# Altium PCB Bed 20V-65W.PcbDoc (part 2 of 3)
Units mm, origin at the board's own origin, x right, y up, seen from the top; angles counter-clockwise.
Board outline 82.02 x 73.67 mm, 2 copper layers (Top Layer, Bottom Layer); 0 components, 1 nets, 2 pads, 0 vias.
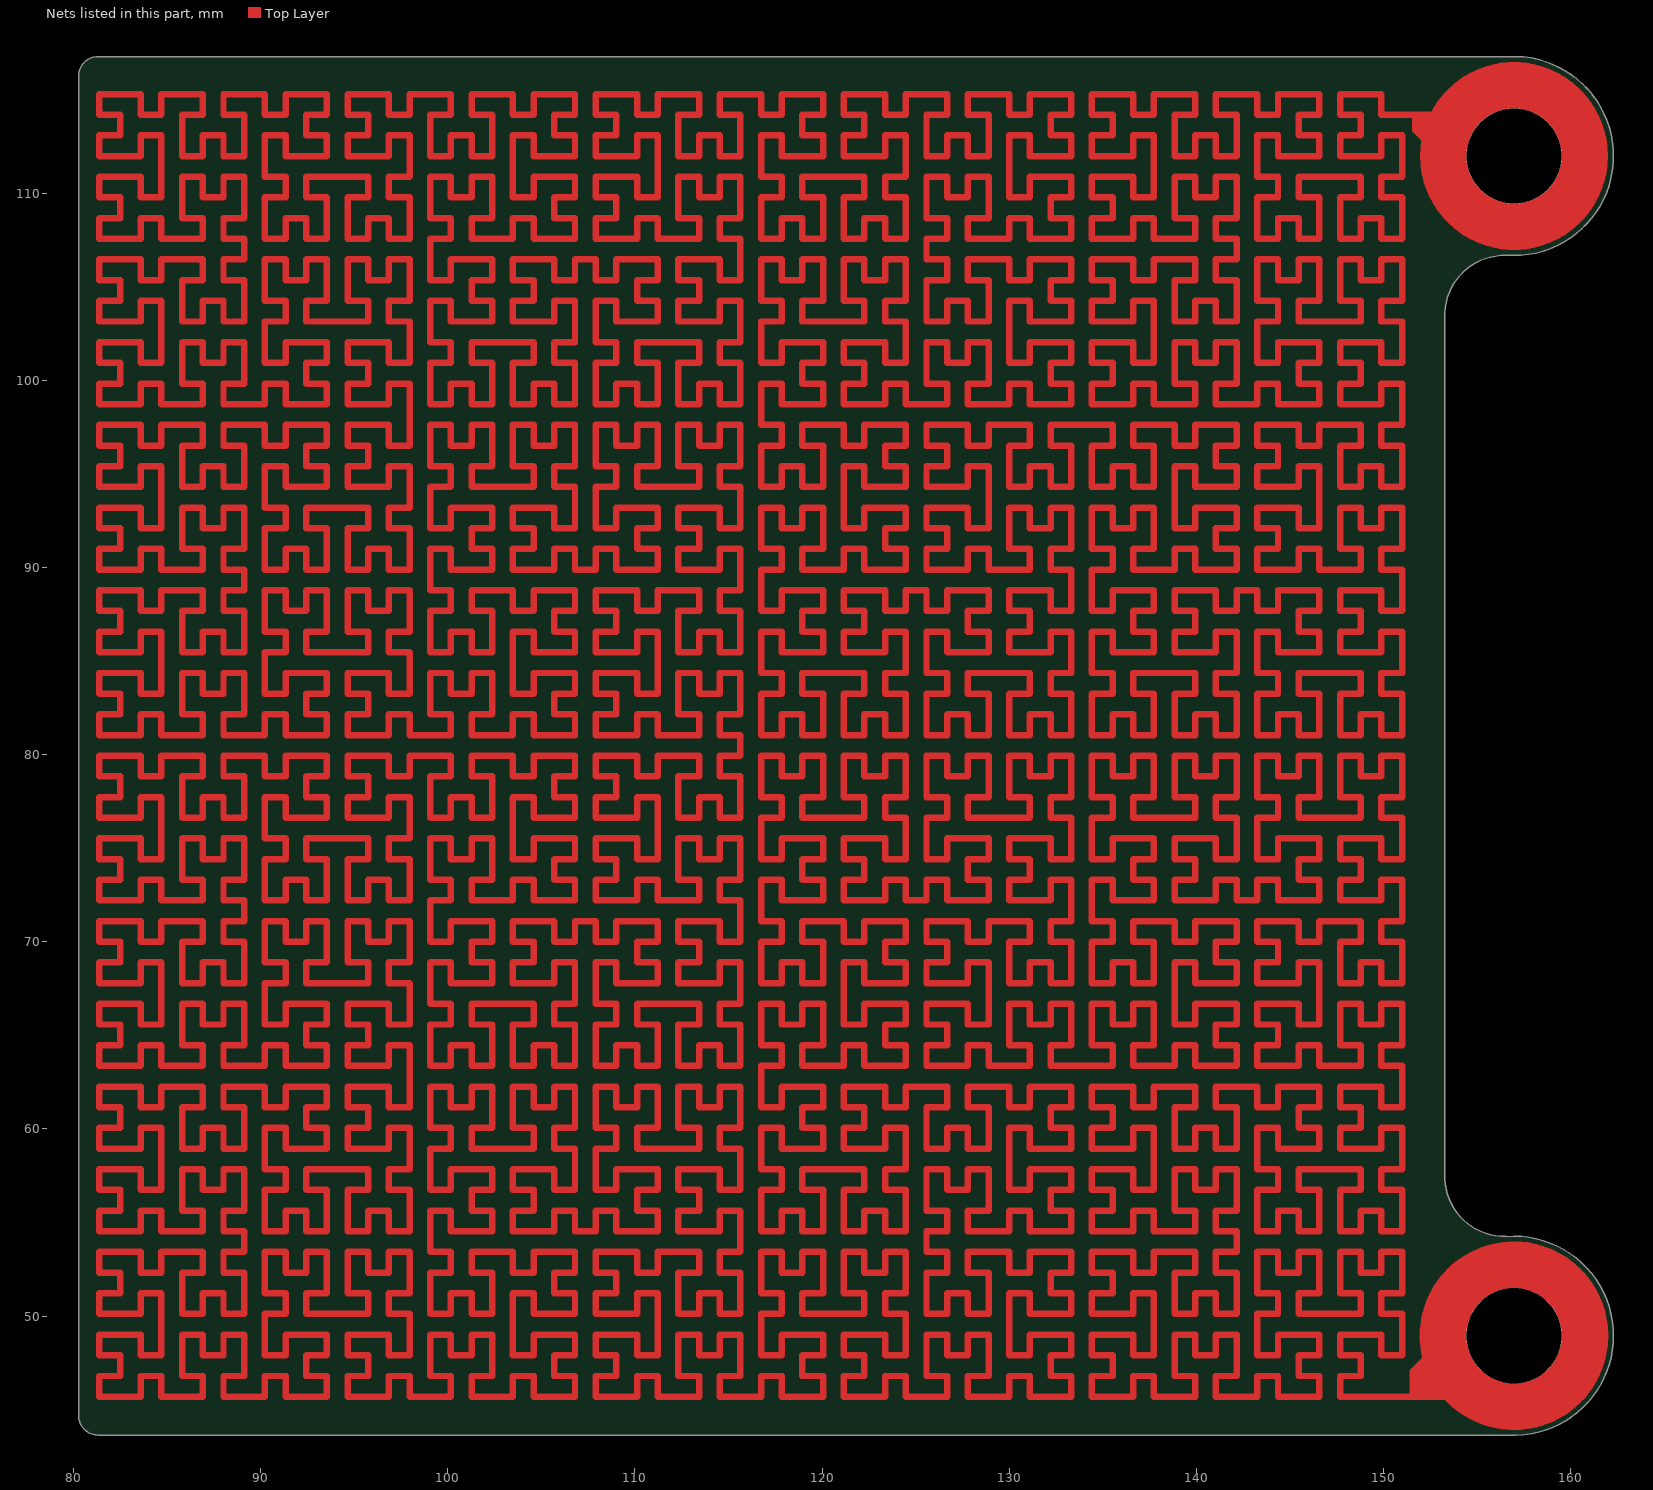
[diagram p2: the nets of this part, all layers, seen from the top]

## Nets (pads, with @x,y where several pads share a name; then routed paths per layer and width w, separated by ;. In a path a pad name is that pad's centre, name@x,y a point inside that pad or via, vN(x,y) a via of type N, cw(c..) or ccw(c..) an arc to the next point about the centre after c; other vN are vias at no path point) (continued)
Bed20V: (continued)
  Top Layer w0.346: 152.248,112.827 151.968,113.106 ; 152.756,112.725 152.222,113.259 152.222,114.193 ; 152.908,112.827 152.451,113.284 152.451,114.193 ; 153.111,112.928 152.756,113.284 152.756,114.193 ; 153.285,48.257 152.778,48.257 151.562,47.041 151.562,45.689 ; 153.34,48.031 152.857,48.031 151.841,47.015 151.841,45.689 ; 153.391,113.055 152.984,113.462 152.984,114.193 ; 153.492,47.727 152.984,47.727 152.121,46.863 152.121,45.689 ; 153.594,47.168 153.187,47.168 152.679,46.66 152.679,45.689 ; 153.594,47.447 153.111,47.447 152.4,46.736 152.4,45.689 ; 153.746,46.914 153.314,46.914 152.959,46.558 152.959,46.33 ; 153.881,114.152 153.881,114.193 152.984,114.193 ; 154.813,46.304 154.788,46.33 152.959,46.33 ; 154.864,45.974 154.82,46.018 152.959,46.018 ; 154.915,45.72 154.884,45.689 152.959,45.689 ; 151.562,45.689 151.841,45.689 ; 151.562,45.689 147.677,45.689 147.677,46.794 148.782,46.794 148.782,47.899 147.677,47.899 147.677,49.004 149.887,49.004 149.887,47.899 150.992,47.899 150.992,50.109 149.887,50.109 149.887,51.214 150.992,51.214 150.992,53.424 149.887,53.424 149.887,52.319 148.782,52.319 148.782,53.424 147.677,53.424 147.677,51.214 148.782,51.214 148.782,50.109 145.467,50.109 145.467,51.214 146.572,51.214 146.572,53.424 145.467,53.424 145.467,52.319 144.362,52.319 144.362,53.424 143.257,53.424 143.257,51.214 144.362,51.214 144.362,50.109 143.257,50.109 143.257,47.899 144.362,47.899 144.362,49.004 146.572,49.004 146.572,47.899 145.467,47.899 145.467,46.794 146.572,46.794 146.572,45.689 144.362,45.689 144.362,46.794 143.257,46.794 143.257,45.689 141.048,45.689 141.048,46.794 142.152,46.794 142.152,49.004 141.048,49.004 141.048,47.899 139.943,47.899 139.943,49.004 138.838,49.004 138.838,46.794 139.943,46.794 139.943,45.689 137.733,45.689 137.733,46.794 136.628,46.794 136.628,45.689 134.418,45.689 134.418,46.794 135.523,46.794 135.523,47.899 134.418,47.899 134.418,49.004 136.628,49.004 136.628,47.899 137.733,47.899 137.733,51.214 136.628,51.214 136.628,50.109 134.418,50.109 134.418,51.214 135.523,51.214 135.523,52.319 134.418,52.319 134.418,53.424 136.628,53.424 136.628,52.319 137.733,52.319 137.733,53.424 139.943,53.424 139.943,52.319 138.838,52.319 138.838,50.109 139.943,50.109 139.943,51.214 141.048,51.214 141.048,50.109 142.152,50.109 142.152,52.319 141.048,52.319 141.048,53.424 142.152,53.424 142.152,54.529 141.048,54.529 141.048,55.633 142.152,55.633 142.152,57.843 141.048,57.843 141.048,56.738 139.943,56.738 139.943,57.843 138.838,57.843 138.838,55.633 139.943,55.633 139.943,54.529 137.733,54.529 137.733,55.633 136.628,55.633 136.628,54.529 134.418,54.529 134.418,55.633 135.523,55.633 135.523,56.738 134.418,56.738 134.418,57.843 136.628,57.843 136.628,56.738 137.733,56.738 137.733,60.053 136.628,60.053 136.628,58.948 134.418,58.948 134.418,60.053 135.523,60.053 135.523,61.158 134.418,61.158 134.418,62.263 136.628,62.263 136.628,61.158 137.733,61.158 137.733,62.263 139.943,62.263 139.943,61.158 138.838,61.158 138.838,58.948 139.943,58.948 139.943,60.053 141.048,60.053 141.048,58.948 142.152,58.948 142.152,61.158 141.048,61.158 141.048,62.263 143.257,62.263 143.257,61.158 144.362,61.158 144.362,62.263 146.572,62.263 146.572,61.158 145.467,61.158 145.467,60.053 146.572,60.053 146.572,58.948 144.362,58.948 144.362,60.053 143.257,60.053 143.257,57.843 144.362,57.843 144.362,56.738 143.257,56.738 143.257,54.529 144.362,54.529 144.362,55.633 145.467,55.633 145.467,54.529 146.572,54.529 146.572,56.738 145.467,56.738 145.467,57.843 148.782,57.843 148.782,56.738 147.677,56.738 147.677,54.529 148.782,54.529 148.782,55.633 149.887,55.633 149.887,54.529 150.992,54.529 150.992,56.738 149.887,56.738 149.887,57.843 150.992,57.843 150.992,60.053 149.887,60.053 149.887,58.948 147.677,58.948 147.677,60.053 148.782,60.053 148.782,61.158 147.677,61.158 147.677,62.263 149.887,62.263 149.887,61.158 150.992,61.158 150.992,63.368 149.887,63.368 149.887,64.473 150.992,64.473 150.992,66.682 149.887,66.682 149.887,65.578 148.782,65.578 148.782,66.682 147.677,66.682 147.677,64.473 148.782,64.473 148.782,63.368 146.572,63.368 146.572,64.473 145.467,64.473 145.467,63.368 143.257,63.368 143.257,64.473 144.362,64.473 144.362,65.578 143.257,65.578 143.257,66.682 145.467,66.682 145.467,65.578 146.572,65.578 146.572,68.892 145.467,68.892 145.467,67.787 143.257,67.787 143.257,68.892 144.362,68.892 144.362,69.997 143.257,69.997 143.257,71.102 145.467,71.102 145.467,69.997 146.572,69.997 146.572,71.102 148.782,71.102 148.782,69.997 147.677,69.997 147.677,67.787 148.782,67.787 148.782,68.892 149.887,68.892 149.887,67.787 150.992,67.787 150.992,69.997 149.887,69.997 149.887,71.102 150.992,71.102 150.992,73.312 149.887,73.312 149.887,72.207 147.677,72.207 147.677,73.312 148.782,73.312 148.782,74.417 147.677,74.417 147.677,75.522 149.887,75.522 149.887,74.417 150.992,74.417 150.992,76.627 149.887,76.627 149.887,77.731 150.992,77.731 150.992,79.941 149.887,79.941 149.887,78.836 148.782,78.836 148.782,79.941 147.677,79.941 147.677,77.731 148.782,77.731 148.782,76.627 145.467,76.627 145.467,77.731 146.572,77.731 146.572,79.941 145.467,79.941 145.467,78.836 144.362,78.836 144.362,79.941 143.257,79.941 143.257,77.731 144.362,77.731 144.362,76.627 143.257,76.627 143.257,74.417 144.362,74.417 144.362,75.522 146.572,75.522 146.572,74.417 145.467,74.417 145.467,73.312 146.572,73.312 146.572,72.207 144.362,72.207 144.362,73.312 143.257,73.312 143.257,72.207 142.152,72.207 142.152,73.312 141.048,73.312 141.048,72.207 138.838,72.207 138.838,73.312 139.943,73.312 139.943,74.417 138.838,74.417 138.838,75.522 141.048,75.522 141.048,74.417 142.152,74.417 142.152,76.627 141.048,76.627 141.048,77.731 142.152,77.731 142.152,79.941 141.048,79.941 141.048,78.836 139.943,78.836 139.943,79.941 138.838,79.941 138.838,77.731 139.943,77.731 139.943,76.627 136.628,76.627 136.628,77.731 137.733,77.731 137.733,79.941 136.628,79.941 136.628,78.836 135.523,78.836 135.523,79.941 134.418,79.941 134.418,77.731 135.523,77.731 135.523,76.627 134.418,76.627 134.418,74.417 135.523,74.417 135.523,75.522 137.733,75.522 137.733,74.417 136.628,74.417 136.628,73.312 137.733,73.312 137.733,72.207 135.523,72.207 135.523,73.312 134.418,73.312 134.418,71.102 135.523,71.102 135.523,69.997 134.418,69.997 134.418,67.787 135.523,67.787 135.523,68.892 136.628,68.892 136.628,67.787 137.733,67.787 137.733,69.997 136.628,69.997 136.628,71.102 138.838,71.102 138.838,69.997 139.943,69.997 139.943,71.102 142.152,71.102 142.152,69.997 141.048,69.997 141.048,68.892 142.152,68.892 142.152,67.787 139.943,67.787 139.943,68.892 138.838,68.892 138.838,65.578 139.943,65.578 139.943,66.682 142.152,66.682 142.152,65.578 141.048,65.578 141.048,64.473 142.152,64.473 142.152,63.368 139.943,63.368 139.943,64.473 138.838,64.473 138.838,63.368 136.628,63.368 136.628,64.473 137.733,64.473 137.733,66.682 136.628,66.682 136.628,65.578 135.523,65.578 135.523,66.682 134.418,66.682 134.418,64.473 135.523,64.473 135.523,63.368 132.208,63.368 132.208,64.473 133.313,64.473 133.313,66.682 132.208,66.682 132.208,65.578 131.103,65.578 131.103,66.682 129.999,66.682 129.999,64.473 131.103,64.473 131.103,63.368 128.894,63.368 128.894,64.473 127.789,64.473 127.789,63.368 125.579,63.368 125.579,64.473 126.684,64.473 126.684,65.578 125.579,65.578 125.579,66.682 127.789,66.682 127.789,65.578 128.894,65.578 128.894,68.892 127.789,68.892 127.789,67.787 125.579,67.787 125.579,68.892 126.684,68.892 126.684,69.997 125.579,69.997 125.579,71.102 127.789,71.102 127.789,69.997 128.894,69.997 128.894,71.102 131.103,71.102 131.103,69.997 129.999,69.997 129.999,67.787 131.103,67.787 131.103,68.892 132.208,68.892 132.208,67.787 133.313,67.787 133.313,69.997 132.208,69.997 132.208,71.102 133.313,71.102 133.313,73.312 132.208,73.312 132.208,72.207 129.999,72.207 129.999,73.312 131.103,73.312 131.103,74.417 129.999,74.417 129.999,75.522 132.208,75.522 132.208,74.417 133.313,74.417 133.313,76.627 132.208,76.627 132.208,77.731 133.313,77.731 133.313,79.941 132.208,79.941 132.208,78.836 131.103,78.836 131.103,79.941 129.999,79.941 129.999,77.731 131.103,77.731 131.103,76.627 127.789,76.627 127.789,77.731 128.894,77.731 128.894,79.941 127.789,79.941 127.789,78.836 126.684,78.836 126.684,79.941 125.579,79.941 125.579,77.731 126.684,77.731 126.684,76.627 125.579,76.627 125.579,74.417 126.684,74.417 126.684,75.522 128.894,75.522 128.894,74.417 127.789,74.417 127.789,73.312 128.894,73.312 128.894,72.207 126.684,72.207 126.684,73.312 125.579,73.312 125.579,72.207 124.474,72.207 124.474,73.312 123.369,73.312 123.369,72.207 121.159,72.207 121.159,73.312 122.264,73.312 122.264,74.417 121.159,74.417 121.159,75.522 123.369,75.522 123.369,74.417 124.474,74.417 124.474,76.627 123.369,76.627 123.369,77.731 124.474,77.731 124.474,79.941 123.369,79.941 123.369,78.836 122.264,78.836 122.264,79.941 121.159,79.941 121.159,77.731 122.264,77.731 122.264,76.627 118.95,76.627 118.95,77.731 120.054,77.731 120.054,79.941 118.95,79.941 118.95,78.836 117.845,78.836 117.845,79.941 116.74,79.941 116.74,77.731 117.845,77.731 117.845,76.627 116.74,76.627 116.74,74.417 117.845,74.417 117.845,75.522 120.054,75.522 120.054,74.417 118.95,74.417 118.95,73.312 120.054,73.312 120.054,72.207 117.845,72.207 117.845,73.312 116.74,73.312 116.74,71.102 117.845,71.102 117.845,69.997 116.74,69.997 116.74,67.787 117.845,67.787 117.845,68.892 118.95,68.892 118.95,67.787 120.054,67.787 120.054,69.997 118.95,69.997 118.95,71.102 121.159,71.102 121.159,69.997 122.264,69.997 122.264,71.102 124.474,71.102 124.474,69.997 123.369,69.997 123.369,68.892 124.474,68.892 124.474,67.787 122.264,67.787 122.264,68.892 121.159,68.892 121.159,65.578 122.264,65.578 122.264,66.682 124.474,66.682 124.474,65.578 123.369,65.578 123.369,64.473 124.474,64.473 124.474,63.368 122.264,63.368 122.264,64.473 121.159,64.473 121.159,63.368 118.95,63.368 118.95,64.473 120.054,64.473 120.054,66.682 118.95,66.682 118.95,65.578 117.845,65.578 117.845,66.682 116.74,66.682 116.74,64.473 117.845,64.473 117.845,63.368 116.74,63.368 116.74,61.158 117.845,61.158 117.845,62.263 120.054,62.263 120.054,61.158 118.95,61.158 118.95,60.053 120.054,60.053 120.054,58.948 117.845,58.948 117.845,60.053 116.74,60.053 116.74,57.843 117.845,57.843 117.845,56.738 116.74,56.738 116.74,54.529 117.845,54.529 117.845,55.633 118.95,55.633 118.95,54.529 120.054,54.529 120.054,56.738 118.95,56.738 118.95,57.843 122.264,57.843 122.264,56.738 121.159,56.738 121.159,54.529 122.264,54.529 122.264,55.633 123.369,55.633 123.369,54.529 124.474,54.529 124.474,56.738 123.369,56.738 123.369,57.843 124.474,57.843 124.474,60.053 123.369,60.053 123.369,58.948 121.159,58.948 121.159,60.053 122.264,60.053 122.264,61.158 121.159,61.158 121.159,62.263 123.369,62.263 123.369,61.158 124.474,61.158 124.474,62.263 126.684,62.263 126.684,61.158 125.579,61.158 125.579,58.948 126.684,58.948 126.684,60.053 127.789,60.053 127.789,58.948 128.894,58.948 128.894,61.158 127.789,61.158 127.789,62.263 129.999,62.263 129.999,61.158 131.103,61.158 131.103,62.263 133.313,62.263 133.313,61.158 132.208,61.158 132.208,60.053 133.313,60.053 133.313,58.948 131.103,58.948 131.103,60.053 129.999,60.053 129.999,56.738 131.103,56.738 131.103,57.843 133.313,57.843 133.313,56.738 132.208,56.738 132.208,55.633 133.313,55.633 133.313,54.529 131.103,54.529 131.103,55.633 129.999,55.633 129.999,54.529 127.789,54.529 127.789,55.633 128.894,55.633 128.894,57.843 127.789,57.843 127.789,56.738 126.684,56.738 126.684,57.843 125.579,57.843 125.579,55.633 126.684,55.633 126.684,54.529 125.579,54.529 125.579,53.424 126.684,53.424 126.684,52.319 125.579,52.319 125.579,50.109 126.684,50.109 126.684,51.214 127.789,51.214 127.789,50.109 128.894,50.109 128.894,52.319 127.789,52.319 127.789,53.424 129.999,53.424 129.999,52.319 131.103,52.319 131.103,53.424 133.313,53.424 133.313,52.319 132.208,52.319 132.208,51.214 133.313,51.214 133.313,50.109 131.103,50.109 131.103,51.214 129.999,51.214 129.999,47.899 131.103,47.899 131.103,49.004 133.313,49.004 133.313,47.899 132.208,47.899 132.208,46.794 133.313,46.794 133.313,45.689 131.103,45.689 131.103,46.794 129.999,46.794 129.999,45.689 127.789,45.689 127.789,46.794 128.894,46.794 128.894,49.004 127.789,49.004 127.789,47.899 126.684,47.899 126.684,49.004 125.579,49.004 125.579,46.794 126.684,46.794 126.684,45.689 124.474,45.689 124.474,46.794 123.369,46.794 123.369,45.689 121.159,45.689 121.159,46.794 122.264,46.794 122.264,47.899 121.159,47.899 121.159,49.004 123.369,49.004 123.369,47.899 124.474,47.899 124.474,50.109 123.369,50.109 123.369,51.214 124.474,51.214 124.474,53.424 123.369,53.424 123.369,52.319 122.264,52.319 122.264,53.424 121.159,53.424 121.159,51.214 122.264,51.214 122.264,50.109 118.95,50.109 118.95,51.214 120.054,51.214 120.054,53.424 118.95,53.424 118.95,52.319 117.845,52.319 117.845,53.424 116.74,53.424 116.74,51.214 117.845,51.214 117.845,50.109 116.74,50.109 116.74,47.899 117.845,47.899 117.845,49.004 120.054,49.004 120.054,47.899 118.95,47.899 118.95,46.794 120.054,46.794 120.054,45.689 117.845,45.689 117.845,46.794 116.74,46.794 116.74,45.689 114.53,45.689 114.53,46.794 115.635,46.794 115.635,49.004 114.53,49.004 114.53,47.899 113.425,47.899 113.425,49.004 112.32,49.004 112.32,46.794 113.425,46.794 113.425,45.689 111.215,45.689 111.215,46.794 110.11,46.794 110.11,45.689 107.901,45.689 107.901,46.794 109.005,46.794 109.005,47.899 107.901,47.899 107.901,49.004 110.11,49.004 110.11,47.899 111.215,47.899 111.215,51.214 110.11,51.214 110.11,50.109 107.901,50.109 107.901,51.214 109.005,51.214 109.005,52.319 107.901,52.319 107.901,53.424 110.11,53.424 110.11,52.319 111.215,52.319 111.215,53.424 113.425,53.424 113.425,52.319 112.32,52.319 112.32,50.109 113.425,50.109 113.425,51.214 114.53,51.214 114.53,50.109 115.635,50.109 115.635,52.319 114.53,52.319 114.53,53.424 115.635,53.424 115.635,55.633 114.53,55.633 114.53,54.529 112.32,54.529 112.32,55.633 113.425,55.633 113.425,56.738 112.32,56.738 112.32,57.843 114.53,57.843 114.53,56.738 115.635,56.738 115.635,58.948 114.53,58.948 114.53,60.053 115.635,60.053 115.635,62.263 114.53,62.263 114.53,61.158 113.425,61.158 113.425,62.263 112.32,62.263 112.32,60.053 113.425,60.053 113.425,58.948 110.11,58.948 110.11,60.053 111.215,60.053 111.215,62.263 110.11,62.263 110.11,61.158 109.005,61.158 109.005,62.263 107.901,62.263 107.901,60.053 109.005,60.053 109.005,58.948 107.901,58.948 107.901,56.738 109.005,56.738 109.005,57.843 111.215,57.843 111.215,56.738 110.11,56.738 110.11,55.633 111.215,55.633 111.215,54.529 109.005,54.529 109.005,55.633 107.901,55.633 107.901,54.529 106.796,54.529 106.796,55.633 105.691,55.633 105.691,54.529 103.481,54.529 103.481,55.633 104.586,55.633 104.586,56.738 103.481,56.738 103.481,57.843 105.691,57.843 105.691,56.738 106.796,56.738 106.796,58.948 105.691,58.948 105.691,60.053 106.796,60.053 106.796,62.263 105.691,62.263 105.691,61.158 104.586,61.158 104.586,62.263 103.481,62.263 103.481,60.053 104.586,60.053 104.586,58.948 101.271,58.948 101.271,60.053 102.376,60.053 102.376,62.263 101.271,62.263 101.271,61.158 100.166,61.158 100.166,62.263 99.061,62.263 99.061,60.053 100.166,60.053 100.166,58.948 99.061,58.948 99.061,56.738 100.166,56.738 100.166,57.843 102.376,57.843 102.376,56.738 101.271,56.738 101.271,55.633 102.376,55.633 102.376,54.529 100.166,54.529 100.166,55.633 99.061,55.633 99.061,53.424 100.166,53.424 100.166,52.319 99.061,52.319 99.061,50.109 100.166,50.109 100.166,51.214 101.271,51.214 101.271,50.109 102.376,50.109 102.376,52.319 101.271,52.319 101.271,53.424 103.481,53.424 103.481,52.319 104.586,52.319 104.586,53.424 106.796,53.424 106.796,52.319 105.691,52.319 105.691,51.214 106.796,51.214 106.796,50.109 104.586,50.109 104.586,51.214 103.481,51.214 103.481,47.899 104.586,47.899 104.586,49.004 106.796,49.004 106.796,47.899 105.691,47.899 105.691,46.794 106.796,46.794 106.796,45.689 104.586,45.689 104.586,46.794 103.481,46.794 103.481,45.689 101.271,45.689 101.271,46.794 102.376,46.794 102.376,49.004 101.271,49.004 101.271,47.899 100.166,47.899 100.166,49.004 99.061,49.004 99.061,46.794 100.166,46.794 100.166,45.689 97.956,45.689 97.956,46.794 96.852,46.794 96.852,45.689 94.642,45.689 94.642,46.794 95.747,46.794 95.747,47.899 94.642,47.899 94.642,49.004 96.852,49.004 96.852,47.899 97.956,47.899 97.956,50.109 96.852,50.109 96.852,51.214 97.956,51.214 97.956,53.424 96.852,53.424 96.852,52.319 95.747,52.319 95.747,53.424 94.642,53.424 94.642,51.214 95.747,51.214 95.747,50.109 92.432,50.109 92.432,51.214 93.537,51.214 93.537,53.424 92.432,53.424 92.432,52.319 91.327,52.319 91.327,53.424 90.222,53.424 90.222,51.214 91.327,51.214 91.327,50.109 90.222,50.109 90.222,47.899 91.327,47.899 91.327,49.004 93.537,49.004 93.537,47.899 92.432,47.899 92.432,46.794 93.537,46.794 93.537,45.689 91.327,45.689 91.327,46.794 90.222,46.794 90.222,45.689 88.012,45.689 88.012,46.794 89.117,46.794 89.117,49.004 88.012,49.004 88.012,47.899 86.907,47.899 86.907,49.004 85.803,49.004 85.803,46.794 86.907,46.794 86.907,45.689 84.698,45.689 84.698,46.794 83.593,46.794 83.593,45.689 81.383,45.689 81.383,46.794 82.488,46.794 82.488,47.899 81.383,47.899 81.383,49.004 83.593,49.004 83.593,47.899 84.698,47.899 84.698,51.214 83.593,51.214 83.593,50.109 81.383,50.109 81.383,51.214 82.488,51.214 82.488,52.319 81.383,52.319 81.383,53.424 83.593,53.424 83.593,52.319 84.698,52.319 84.698,53.424 86.907,53.424 86.907,52.319 85.803,52.319 85.803,50.109 86.907,50.109 86.907,51.214 88.012,51.214 88.012,50.109 89.117,50.109 89.117,52.319 88.012,52.319 88.012,53.424 89.117,53.424 89.117,54.529 88.012,54.529 88.012,55.633 89.117,55.633 89.117,57.843 88.012,57.843 88.012,56.738 86.907,56.738 86.907,57.843 85.803,57.843 85.803,55.633 86.907,55.633 86.907,54.529 84.698,54.529 84.698,55.633 83.593,55.633 83.593,54.529 81.383,54.529 81.383,55.633 82.488,55.633 82.488,56.738 81.383,56.738 81.383,57.843 83.593,57.843 83.593,56.738 84.698,56.738 84.698,60.053 83.593,60.053 83.593,58.948 81.383,58.948 81.383,60.053 82.488,60.053 82.488,61.158 81.383,61.158 81.383,62.263 83.593,62.263 83.593,61.158 84.698,61.158 84.698,62.263 86.907,62.263 86.907,61.158 85.803,61.158 85.803,58.948 86.907,58.948 86.907,60.053 88.012,60.053 88.012,58.948 89.117,58.948 89.117,61.158 88.012,61.158 88.012,62.263 90.222,62.263 90.222,61.158 91.327,61.158 91.327,62.263 93.537,62.263 93.537,61.158 92.432,61.158 92.432,60.053 93.537,60.053 93.537,58.948 91.327,58.948 91.327,60.053 90.222,60.053 90.222,57.843 91.327,57.843 91.327,56.738 90.222,56.738 90.222,54.529 91.327,54.529 91.327,55.633 92.432,55.633 92.432,54.529 93.537,54.529 93.537,56.738 92.432,56.738 92.432,57.843 95.747,57.843 95.747,56.738 94.642,56.738 94.642,54.529 95.747,54.529 95.747,55.633 96.852,55.633 96.852,54.529 97.956,54.529 97.956,56.738 96.852,56.738 96.852,57.843 97.956,57.843 97.956,60.053 96.852,60.053 96.852,58.948 94.642,58.948 94.642,60.053 95.747,60.053 95.747,61.158 94.642,61.158 94.642,62.263 96.852,62.263 96.852,61.158 97.956,61.158 97.956,64.473 96.852,64.473 96.852,63.368 94.642,63.368 94.642,64.473 95.747,64.473 95.747,65.578 94.642,65.578 94.642,66.682 96.852,66.682 96.852,65.578 97.956,65.578 97.956,67.787 96.852,67.787 96.852,68.892 97.956,68.892 97.956,71.102 96.852,71.102 96.852,69.997 95.747,69.997 95.747,71.102 94.642,71.102 94.642,68.892 95.747,68.892 95.747,67.787 92.432,67.787 92.432,68.892 93.537,68.892 93.537,71.102 92.432,71.102 92.432,69.997 91.327,69.997 91.327,71.102 90.222,71.102 90.222,68.892 91.327,68.892 91.327,67.787 90.222,67.787 90.222,65.578 91.327,65.578 91.327,66.682 93.537,66.682 93.537,65.578 92.432,65.578 92.432,64.473 93.537,64.473 93.537,63.368 91.327,63.368 91.327,64.473 90.222,64.473 90.222,63.368 88.012,63.368 88.012,64.473 89.117,64.473 89.117,66.682 88.012,66.682 88.012,65.578 86.907,65.578 86.907,66.682 85.803,66.682 85.803,64.473 86.907,64.473 86.907,63.368 84.698,63.368 84.698,64.473 83.593,64.473 83.593,63.368 81.383,63.368 81.383,64.473 82.488,64.473 82.488,65.578 81.383,65.578 81.383,66.682 83.593,66.682 83.593,65.578 84.698,65.578 84.698,68.892 83.593,68.892 83.593,67.787 81.383,67.787 81.383,68.892 82.488,68.892 82.488,69.997 81.383,69.997 81.383,71.102 83.593,71.102 83.593,69.997 84.698,69.997 84.698,71.102 86.907,71.102 86.907,69.997 85.803,69.997 85.803,67.787 86.907,67.787 86.907,68.892 88.012,68.892 88.012,67.787 89.117,67.787 89.117,69.997 88.012,69.997 88.012,71.102 89.117,71.102 89.117,72.207 88.012,72.207 88.012,73.312 89.117,73.312 89.117,75.522 88.012,75.522 88.012,74.417 86.907,74.417 86.907,75.522 85.803,75.522 85.803,73.312 86.907,73.312 86.907,72.207 84.698,72.207 84.698,73.312 83.593,73.312 83.593,72.207 81.383,72.207 81.383,73.312 82.488,73.312 82.488,74.417 81.383,74.417 81.383,75.522 83.593,75.522 83.593,74.417 84.698,74.417 84.698,77.731 83.593,77.731 83.593,76.627 81.383,76.627 81.383,77.731 82.488,77.731 82.488,78.836 81.383,78.836 81.383,79.941 83.593,79.941 83.593,78.836 84.698,78.836 84.698,79.941 86.907,79.941 86.907,78.836 85.803,78.836 85.803,76.627 86.907,76.627 86.907,77.731 88.012,77.731 88.012,76.627 89.117,76.627 89.117,78.836 88.012,78.836 88.012,79.941 90.222,79.941 90.222,78.836 91.327,78.836 91.327,79.941 93.537,79.941 93.537,78.836 92.432,78.836 92.432,77.731 93.537,77.731 93.537,76.627 91.327,76.627 91.327,77.731 90.222,77.731 90.222,75.522 91.327,75.522 91.327,74.417 90.222,74.417 90.222,72.207 91.327,72.207 91.327,73.312 92.432,73.312 92.432,72.207 93.537,72.207 93.537,74.417 92.432,74.417 92.432,75.522 95.747,75.522 95.747,74.417 94.642,74.417 94.642,72.207 95.747,72.207 95.747,73.312 96.852,73.312 96.852,72.207 97.956,72.207 97.956,74.417 96.852,74.417 96.852,75.522 97.956,75.522 97.956,77.731 96.852,77.731 96.852,76.627 94.642,76.627 94.642,77.731 95.747,77.731 95.747,78.836 94.642,78.836 94.642,79.941 96.852,79.941 96.852,78.836 97.956,78.836 97.956,79.941 100.166,79.941 100.166,78.836 99.061,78.836 99.061,76.627 100.166,76.627 100.166,77.731 101.271,77.731 101.271,76.627 102.376,76.627 102.376,78.836 101.271,78.836 101.271,79.941 103.481,79.941 103.481,78.836 104.586,78.836 104.586,79.941 106.796,79.941 106.796,78.836 105.691,78.836 105.691,77.731 106.796,77.731 106.796,76.627 104.586,76.627 104.586,77.731 103.481,77.731 103.481,74.417 104.586,74.417 104.586,75.522 106.796,75.522 106.796,74.417 105.691,74.417 105.691,73.312 106.796,73.312 106.796,72.207 104.586,72.207 104.586,73.312 103.481,73.312 103.481,72.207 101.271,72.207 101.271,73.312 102.376,73.312 102.376,75.522 101.271,75.522 101.271,74.417 100.166,74.417 100.166,75.522 99.061,75.522 99.061,73.312 100.166,73.312 100.166,72.207 99.061,72.207 99.061,69.997 100.166,69.997 100.166,71.102 102.376,71.102 102.376,69.997 101.271,69.997 101.271,68.892 102.376,68.892 102.376,67.787 100.166,67.787 100.166,68.892 99.061,68.892 99.061,66.682 100.166,66.682 100.166,65.578 99.061,65.578 99.061,63.368 100.166,63.368 100.166,64.473 101.271,64.473 101.271,63.368 102.376,63.368 102.376,65.578 101.271,65.578 101.271,66.682 104.586,66.682 104.586,65.578 103.481,65.578 103.481,63.368 104.586,63.368 104.586,64.473 105.691,64.473 105.691,63.368 106.796,63.368 106.796,65.578 105.691,65.578 105.691,66.682 106.796,66.682 106.796,68.892 105.691,68.892 105.691,67.787 103.481,67.787 103.481,68.892 104.586,68.892 104.586,69.997 103.481,69.997 103.481,71.102 105.691,71.102 105.691,69.997 106.796,69.997 106.796,71.102 107.901,71.102 107.901,69.997 109.005,69.997 109.005,71.102 111.215,71.102 111.215,69.997 110.11,69.997 110.11,68.892 111.215,68.892 111.215,67.787 109.005,67.787 109.005,68.892 107.901,68.892 107.901,66.682 109.005,66.682 109.005,65.578 107.901,65.578 107.901,63.368 109.005,63.368 109.005,64.473 110.11,64.473 110.11,63.368 111.215,63.368 111.215,65.578 110.11,65.578 110.11,66.682 113.425,66.682 113.425,65.578 112.32,65.578 112.32,63.368 113.425,63.368 113.425,64.473 114.53,64.473 114.53,63.368 115.635,63.368 115.635,65.578 114.53,65.578 114.53,66.682 115.635,66.682 115.635,68.892 114.53,68.892 114.53,67.787 112.32,67.787 112.32,68.892 113.425,68.892 113.425,69.997 112.32,69.997 112.32,71.102 114.53,71.102 114.53,69.997 115.635,69.997 115.635,72.207 114.53,72.207 114.53,73.312 115.635,73.312 115.635,75.522 114.53,75.522 114.53,74.417 113.425,74.417 113.425,75.522 112.32,75.522 112.32,73.312 113.425,73.312 113.425,72.207 111.215,72.207 111.215,73.312 110.11,73.312 110.11,72.207 107.901,72.207 107.901,73.312 109.005,73.312 109.005,74.417 107.901,74.417 107.901,75.522 110.11,75.522 110.11,74.417 111.215,74.417 111.215,77.731 110.11,77.731 110.11,76.627 107.901,76.627 107.901,77.731 109.005,77.731 109.005,78.836 107.901,78.836 107.901,79.941 110.11,79.941 110.11,78.836 111.215,78.836 111.215,79.941 113.425,79.941 113.425,78.836 112.32,78.836 112.32,76.627 113.425,76.627 113.425,77.731 114.53,77.731 114.53,76.627 115.635,76.627 115.635,78.836 114.53,78.836 114.53,79.941 115.635,79.941 115.635,81.046 114.53,81.046 114.53,82.151 115.635,82.151 115.635,84.361 114.53,84.361 114.53,83.256 113.425,83.256 113.425,84.361 112.32,84.361 112.32,82.151 113.425,82.151 113.425,81.046 111.215,81.046 111.215,82.151 110.11,82.151 110.11,81.046 107.901,81.046 107.901,82.151 109.005,82.151 109.005,83.256 107.901,83.256 107.901,84.361 110.11,84.361 110.11,83.256 111.215,83.256 111.215,86.571 110.11,86.571 110.11,85.466 107.901,85.466 107.901,86.571 109.005,86.571 109.005,87.676 107.901,87.676 107.901,88.78 110.11,88.78 110.11,87.676 111.215,87.676 111.215,88.78 113.425,88.78 113.425,87.676 112.32,87.676 112.32,85.466 113.425,85.466 113.425,86.571 114.53,86.571 114.53,85.466 115.635,85.466 115.635,87.676 114.53,87.676 114.53,88.78 115.635,88.78 115.635,90.99 114.53,90.99 114.53,89.885 112.32,89.885 112.32,90.99 113.425,90.99 113.425,92.095 112.32,92.095 112.32,93.2 114.53,93.2 114.53,92.095 115.635,92.095 115.635,94.305 114.53,94.305 114.53,95.41 115.635,95.41 115.635,97.62 114.53,97.62 114.53,96.515 113.425,96.515 113.425,97.62 112.32,97.62 112.32,95.41 113.425,95.41 113.425,94.305 110.11,94.305 110.11,95.41 111.215,95.41 111.215,97.62 110.11,97.62 110.11,96.515 109.005,96.515 109.005,97.62 107.901,97.62 107.901,95.41 109.005,95.41 109.005,94.305 107.901,94.305 107.901,92.095 109.005,92.095 109.005,93.2 111.215,93.2 111.215,92.095 110.11,92.095 110.11,90.99 111.215,90.99 111.215,89.885 109.005,89.885 109.005,90.99 107.901,90.99 107.901,89.885 106.796,89.885 106.796,90.99 105.691,90.99 105.691,89.885 103.481,89.885 103.481,90.99 104.586,90.99 104.586,92.095 103.481,92.095 103.481,93.2 105.691,93.2 105.691,92.095 106.796,92.095 106.796,94.305 105.691,94.305 105.691,95.41 106.796,95.41 106.796,97.62 105.691,97.62 105.691,96.515 104.586,96.515 104.586,97.62 103.481,97.62 103.481,95.41 104.586,95.41 104.586,94.305 101.271,94.305 101.271,95.41 102.376,95.41 102.376,97.62 101.271,97.62 101.271,96.515 100.166,96.515 100.166,97.62 99.061,97.62 99.061,95.41 100.166,95.41 100.166,94.305 99.061,94.305 99.061,92.095 100.166,92.095 100.166,93.2 102.376,93.2 102.376,92.095 101.271,92.095 101.271,90.99 102.376,90.99 102.376,89.885 100.166,89.885 100.166,90.99 99.061,90.99 99.061,88.78 100.166,88.78 100.166,87.676 99.061,87.676 99.061,85.466 100.166,85.466 100.166,86.571 101.271,86.571 101.271,85.466 102.376,85.466 102.376,87.676 101.271,87.676 101.271,88.78 103.481,88.78 103.481,87.676 104.586,87.676 104.586,88.78 106.796,88.78 106.796,87.676 105.691,87.676 105.691,86.571 106.796,86.571 106.796,85.466 104.586,85.466 104.586,86.571 103.481,86.571 103.481,83.256 104.586,83.256 104.586,84.361 106.796,84.361 106.796,83.256 105.691,83.256 105.691,82.151 106.796,82.151 106.796,81.046 104.586,81.046 104.586,82.151 103.481,82.151 103.481,81.046 101.271,81.046 101.271,82.151 102.376,82.151 102.376,84.361 101.271,84.361 101.271,83.256 100.166,83.256 100.166,84.361 99.061,84.361 99.061,82.151 100.166,82.151 100.166,81.046 97.956,81.046 97.956,82.151 96.852,82.151 96.852,81.046 94.642,81.046 94.642,82.151 95.747,82.151 95.747,83.256 94.642,83.256 94.642,84.361 96.852,84.361 96.852,83.256 97.956,83.256 97.956,85.466 96.852,85.466 96.852,86.571 97.956,86.571 97.956,88.78 96.852,88.78 96.852,87.676 95.747,87.676 95.747,88.78 94.642,88.78 94.642,86.571 95.747,86.571 95.747,85.466 92.432,85.466 92.432,86.571 93.537,86.571 93.537,88.78 92.432,88.78 92.432,87.676 91.327,87.676 91.327,88.78 90.222,88.78 90.222,86.571 91.327,86.571 91.327,85.466 90.222,85.466 90.222,83.256 91.327,83.256 91.327,84.361 93.537,84.361 93.537,83.256 92.432,83.256 92.432,82.151 93.537,82.151 93.537,81.046 91.327,81.046 91.327,82.151 90.222,82.151 90.222,81.046 88.012,81.046 88.012,82.151 89.117,82.151 89.117,84.361 88.012,84.361 88.012,83.256 86.907,83.256 86.907,84.361 85.803,84.361 85.803,82.151 86.907,82.151 86.907,81.046 84.698,81.046 84.698,82.151 83.593,82.151 83.593,81.046 81.383,81.046 81.383,82.151 82.488,82.151 82.488,83.256 81.383,83.256 81.383,84.361 83.593,84.361 83.593,83.256 84.698,83.256 84.698,86.571 83.593,86.571 83.593,85.466 81.383,85.466 81.383,86.571 82.488,86.571 82.488,87.676 81.383,87.676 81.383,88.78 83.593,88.78 83.593,87.676 84.698,87.676 84.698,88.78 86.907,88.78 86.907,87.676 85.803,87.676 85.803,85.466 86.907,85.466 86.907,86.571 88.012,86.571 88.012,85.466 89.117,85.466 89.117,87.676 88.012,87.676 88.012,88.78 89.117,88.78 89.117,89.885 88.012,89.885 88.012,90.99 89.117,90.99 89.117,93.2 88.012,93.2 88.012,92.095 86.907,92.095 86.907,93.2 85.803,93.2 85.803,90.99 86.907,90.99 86.907,89.885 84.698,89.885 84.698,90.99 83.593,90.99 83.593,89.885 81.383,89.885 81.383,90.99 82.488,90.99 82.488,92.095 81.383,92.095 81.383,93.2 83.593,93.2 83.593,92.095 84.698,92.095 84.698,95.41 83.593,95.41 83.593,94.305 81.383,94.305 81.383,95.41 82.488,95.41 82.488,96.515 81.383,96.515 81.383,97.62 83.593,97.62 83.593,96.515 84.698,96.515 84.698,97.62 86.907,97.62 86.907,96.515 85.803,96.515 85.803,94.305 86.907,94.305 86.907,95.41 88.012,95.41 88.012,94.305 89.117,94.305 89.117,96.515 88.012,96.515 88.012,97.62 90.222,97.62 90.222,96.515 91.327,96.515 91.327,97.62 93.537,97.62 93.537,96.515 92.432,96.515 92.432,95.41 93.537,95.41 93.537,94.305 91.327,94.305 91.327,95.41 90.222,95.41 90.222,93.2 91.327,93.2 91.327,92.095 90.222,92.095 90.222,89.885 91.327,89.885 91.327,90.99 92.432,90.99 92.432,89.885 93.537,89.885 93.537,92.095 92.432,92.095 92.432,93.2 95.747,93.2 95.747,92.095 94.642,92.095 94.642,89.885 95.747,89.885 95.747,90.99 96.852,90.99 96.852,89.885 97.956,89.885 97.956,92.095 96.852,92.095 96.852,93.2 97.956,93.2 97.956,95.41 96.852,95.41 96.852,94.305 94.642,94.305 94.642,95.41 95.747,95.41 95.747,96.515 94.642,96.515 94.642,97.62 96.852,97.62 96.852,96.515 97.956,96.515 97.956,99.829 96.852,99.829 96.852,98.725 94.642,98.725 94.642,99.829 95.747,99.829 95.747,100.934 94.642,100.934 94.642,102.039 96.852,102.039 96.852,100.934 97.956,100.934 97.956,103.144 96.852,103.144 96.852,104.249 97.956,104.249 97.956,106.459 96.852,106.459 96.852,105.354 95.747,105.354 95.747,106.459 94.642,106.459 94.642,104.249 95.747,104.249 95.747,103.144 92.432,103.144 92.432,104.249 93.537,104.249 93.537,106.459 92.432,106.459 92.432,105.354 91.327,105.354 91.327,106.459 90.222,106.459 90.222,104.249 91.327,104.249 91.327,103.144 90.222,103.144 90.222,100.934 91.327,100.934 91.327,102.039 93.537,102.039 93.537,100.934 92.432,100.934 92.432,99.829 93.537,99.829 93.537,98.725 91.327,98.725 91.327,99.829 90.222,99.829 90.222,98.725 88.012,98.725 88.012,99.829 89.117,99.829 89.117,102.039 88.012,102.039 88.012,100.934 86.907,100.934 86.907,102.039 85.803,102.039 85.803,99.829 86.907,99.829 86.907,98.725 84.698,98.725 84.698,99.829 83.593,99.829 83.593,98.725 81.383,98.725 81.383,99.829 82.488,99.829 82.488,100.934 81.383,100.934 81.383,102.039 83.593,102.039 83.593,100.934 84.698,100.934 84.698,104.249 83.593,104.249 83.593,103.144 81.383,103.144 81.383,104.249 82.488,104.249 82.488,105.354 81.383,105.354 81.383,106.459 83.593,106.459 83.593,105.354 84.698,105.354 84.698,106.459 86.907,106.459 86.907,105.354 85.803,105.354 85.803,103.144 86.907,103.144 86.907,104.249 88.012,104.249 88.012,103.144 89.117,103.144 89.117,105.354 88.012,105.354 88.012,106.459 89.117,106.459 89.117,107.564 88.012,107.564 88.012,108.669 89.117,108.669 89.117,110.878 88.012,110.878 88.012,109.774 86.907,109.774 86.907,110.878 85.803,110.878 85.803,108.669 86.907,108.669 86.907,107.564 84.698,107.564 84.698,108.669 83.593,108.669 83.593,107.564 81.383,107.564 81.383,108.669 82.488,108.669 82.488,109.774 81.383,109.774 81.383,110.878 83.593,110.878 83.593,109.774 84.698,109.774 84.698,113.088 83.593,113.088 83.593,111.983 81.383,111.983 81.383,113.088 82.488,113.088 82.488,114.193 81.383,114.193 81.383,115.298 83.593,115.298 83.593,114.193 84.698,114.193 84.698,115.298 86.907,115.298 86.907,114.193 85.803,114.193 85.803,111.983 86.907,111.983 86.907,113.088 88.012,113.088 88.012,111.983 89.117,111.983 89.117,114.193 88.012,114.193 88.012,115.298 90.222,115.298 90.222,114.193 91.327,114.193 91.327,115.298 93.537,115.298 93.537,114.193 92.432,114.193 92.432,113.088 93.537,113.088 93.537,111.983 91.327,111.983 91.327,113.088 90.222,113.088 90.222,110.878 91.327,110.878 91.327,109.774 90.222,109.774 90.222,107.564 91.327,107.564 91.327,108.669 92.432,108.669 92.432,107.564 93.537,107.564 93.537,109.774 92.432,109.774 92.432,110.878 95.747,110.878 95.747,109.774 94.642,109.774 94.642,107.564 95.747,107.564 95.747,108.669 96.852,108.669 96.852,107.564 97.956,107.564 97.956,109.774 96.852,109.774 96.852,110.878 97.956,110.878 97.956,113.088 96.852,113.088 96.852,111.983 94.642,111.983 94.642,113.088 95.747,113.088 95.747,114.193 94.642,114.193 94.642,115.298 96.852,115.298 96.852,114.193 97.956,114.193 97.956,115.298 100.166,115.298 100.166,114.193 99.061,114.193 99.061,111.983 100.166,111.983 100.166,113.088 101.271,113.088 101.271,111.983 102.376,111.983 102.376,114.193 101.271,114.193 101.271,115.298 103.481,115.298 103.481,114.193 104.586,114.193 104.586,115.298 106.796,115.298 106.796,114.193 105.691,114.193 105.691,113.088 106.796,113.088 106.796,111.983 104.586,111.983 104.586,113.088 103.481,113.088 103.481,109.774 104.586,109.774 104.586,110.878 106.796,110.878 106.796,109.774 105.691,109.774 105.691,108.669 106.796,108.669 106.796,107.564 104.586,107.564 104.586,108.669 103.481,108.669 103.481,107.564 101.271,107.564 101.271,108.669 102.376,108.669 102.376,110.878 101.271,110.878 101.271,109.774 100.166,109.774 100.166,110.878 99.061,110.878 99.061,108.669 100.166,108.669 100.166,107.564 99.061,107.564 99.061,105.354 100.166,105.354 100.166,106.459 102.376,106.459 102.376,105.354 101.271,105.354 101.271,104.249 102.376,104.249 102.376,103.144 100.166,103.144 100.166,104.249 99.061,104.249 99.061,102.039 100.166,102.039 100.166,100.934 99.061,100.934 99.061,98.725 100.166,98.725 100.166,99.829 101.271,99.829 101.271,98.725 102.376,98.725 102.376,100.934 101.271,100.934 101.271,102.039 104.586,102.039 104.586,100.934 103.481,100.934 103.481,98.725 104.586,98.725 104.586,99.829 105.691,99.829 105.691,98.725 106.796,98.725 106.796,100.934 105.691,100.934 105.691,102.039 106.796,102.039 106.796,104.249 105.691,104.249 105.691,103.144 103.481,103.144 103.481,104.249 104.586,104.249 104.586,105.354 103.481,105.354 103.481,106.459 105.691,106.459 105.691,105.354 106.796,105.354 106.796,106.459 107.901,106.459 107.901,105.354 109.005,105.354 109.005,106.459 111.215,106.459 111.215,105.354 110.11,105.354 110.11,104.249 111.215,104.249 111.215,103.144 109.005,103.144 109.005,104.249 107.901,104.249 107.901,102.039 109.005,102.039 109.005,100.934 107.901,100.934 107.901,98.725 109.005,98.725 109.005,99.829 110.11,99.829 110.11,98.725 111.215,98.725 111.215,100.934 110.11,100.934 110.11,102.039 113.425,102.039 113.425,100.934 112.32,100.934 112.32,98.725 113.425,98.725 113.425,99.829 114.53,99.829 114.53,98.725 115.635,98.725 115.635,100.934 114.53,100.934 114.53,102.039 115.635,102.039 115.635,104.249 114.53,104.249 114.53,103.144 112.32,103.144 112.32,104.249 113.425,104.249 113.425,105.354 112.32,105.354 112.32,106.459 114.53,106.459 114.53,105.354 115.635,105.354 115.635,107.564 114.53,107.564 114.53,108.669 115.635,108.669 115.635,110.878 114.53,110.878 114.53,109.774 113.425,109.774 113.425,110.878 112.32,110.878 112.32,108.669 113.425,108.669 113.425,107.564 111.215,107.564 111.215,108.669 110.11,108.669 110.11,107.564 107.901,107.564 107.901,108.669 109.005,108.669 109.005,109.774 107.901,109.774 107.901,110.878 110.11,110.878 110.11,109.774 111.215,109.774 111.215,113.088 110.11,113.088 110.11,111.983 107.901,111.983 107.901,113.088 109.005,113.088 109.005,114.193 107.901,114.193 107.901,115.298 110.11,115.298 110.11,114.193 111.215,114.193 111.215,115.298 113.425,115.298 113.425,114.193 112.32,114.193 112.32,111.983 113.425,111.983 113.425,113.088 114.53,113.088 114.53,111.983 115.635,111.983 115.635,114.193 114.53,114.193 114.53,115.298 116.74,115.298 116.74,114.193 117.845,114.193 117.845,115.298 120.054,115.298 120.054,114.193 118.95,114.193 118.95,113.088 120.054,113.088 120.054,111.983 117.845,111.983 117.845,113.088 116.74,113.088 116.74,110.878 117.845,110.878 117.845,109.774 116.74,109.774 116.74,107.564 117.845,107.564 117.845,108.669 118.95,108.669 118.95,107.564 120.054,107.564 120.054,109.774 118.95,109.774 118.95,110.878 122.264,110.878 122.264,109.774 121.159,109.774 121.159,107.564 122.264,107.564 122.264,108.669 123.369,108.669 123.369,107.564 124.474,107.564 124.474,109.774 123.369,109.774 123.369,110.878 124.474,110.878 124.474,113.088 123.369,113.088 123.369,111.983 121.159,111.983 121.159,113.088 122.264,113.088 122.264,114.193 121.159,114.193 121.159,115.298 123.369,115.298 123.369,114.193 124.474,114.193 124.474,115.298 126.684,115.298 126.684,114.193 125.579,114.193 125.579,111.983 126.684,111.983 126.684,113.088 127.789,113.088 127.789,111.983 128.894,111.983 128.894,114.193 127.789,114.193 127.789,115.298 129.999,115.298 129.999,114.193 131.103,114.193 131.103,115.298 133.313,115.298 133.313,114.193 132.208,114.193 132.208,113.088 133.313,113.088 133.313,111.983 131.103,111.983 131.103,113.088 129.999,113.088 129.999,109.774 131.103,109.774 131.103,110.878 133.313,110.878 133.313,109.774 132.208,109.774 132.208,108.669 133.313,108.669 133.313,107.564 131.103,107.564 131.103,108.669 129.999,108.669 129.999,107.564 127.789,107.564 127.789,108.669 128.894,108.669 128.894,110.878 127.789,110.878 127.789,109.774 126.684,109.774 126.684,110.878 125.579,110.878 125.579,108.669 126.684,108.669 126.684,107.564 125.579,107.564 125.579,106.459 126.684,106.459 126.684,105.354 125.579,105.354 125.579,103.144 126.684,103.144 126.684,104.249 127.789,104.249 127.789,103.144 128.894,103.144 128.894,105.354 127.789,105.354 127.789,106.459 129.999,106.459 129.999,105.354 131.103,105.354 131.103,106.459 133.313,106.459 133.313,105.354 132.208,105.354 132.208,104.249 133.313,104.249 133.313,103.144 131.103,103.144 131.103,104.249 129.999,104.249 129.999,100.934 131.103,100.934 131.103,102.039 133.313,102.039 133.313,100.934 132.208,100.934 132.208,99.829 133.313,99.829 133.313,98.725 131.103,98.725 131.103,99.829 129.999,99.829 129.999,98.725 127.789,98.725 127.789,99.829 128.894,99.829 128.894,102.039 127.789,102.039 127.789,100.934 126.684,100.934 126.684,102.039 125.579,102.039 125.579,99.829 126.684,99.829 126.684,98.725 124.474,98.725 124.474,99.829 123.369,99.829 123.369,98.725 121.159,98.725 121.159,99.829 122.264,99.829 122.264,100.934 121.159,100.934 121.159,102.039 123.369,102.039 123.369,100.934 124.474,100.934 124.474,103.144 123.369,103.144 123.369,104.249 124.474,104.249 124.474,106.459 123.369,106.459 123.369,105.354 122.264,105.354 122.264,106.459 121.159,106.459 121.159,104.249 122.264,104.249 122.264,103.144 118.95,103.144 118.95,104.249 120.054,104.249 120.054,106.459 118.95,106.459 118.95,105.354 117.845,105.354 117.845,106.459 116.74,106.459 116.74,104.249 117.845,104.249 117.845,103.144 116.74,103.144 116.74,100.934 117.845,100.934 117.845,102.039 120.054,102.039 120.054,100.934 118.95,100.934 118.95,99.829 120.054,99.829 120.054,98.725 117.845,98.725 117.845,99.829 116.74,99.829 116.74,97.62 117.845,97.62 117.845,96.515 116.74,96.515 116.74,94.305 117.845,94.305 117.845,95.41 118.95,95.41 118.95,94.305 120.054,94.305 120.054,96.515 118.95,96.515 118.95,97.62 121.159,97.62 121.159,96.515 122.264,96.515 122.264,97.62 124.474,97.62 124.474,96.515 123.369,96.515 123.369,95.41 124.474,95.41 124.474,94.305 122.264,94.305 122.264,95.41 121.159,95.41 121.159,92.095 122.264,92.095 122.264,93.2 124.474,93.2 124.474,92.095 123.369,92.095 123.369,90.99 124.474,90.99 124.474,89.885 122.264,89.885 122.264,90.99 121.159,90.99 121.159,89.885 118.95,89.885 118.95,90.99 120.054,90.99 120.054,93.2 118.95,93.2 118.95,92.095 117.845,92.095 117.845,93.2 116.74,93.2 116.74,90.99 117.845,90.99 117.845,89.885 116.74,89.885 116.74,87.676 117.845,87.676 117.845,88.78 120.054,88.78 120.054,87.676 118.95,87.676 118.95,86.571 120.054,86.571 120.054,85.466 117.845,85.466 117.845,86.571 116.74,86.571 116.74,84.361 117.845,84.361 117.845,83.256 116.74,83.256 116.74,81.046 117.845,81.046 117.845,82.151 118.95,82.151 118.95,81.046 120.054,81.046 120.054,83.256 118.95,83.256 118.95,84.361 122.264,84.361 122.264,83.256 121.159,83.256 121.159,81.046 122.264,81.046 122.264,82.151 123.369,82.151 123.369,81.046 124.474,81.046 124.474,83.256 123.369,83.256 123.369,84.361 124.474,84.361 124.474,86.571 123.369,86.571 123.369,85.466 121.159,85.466 121.159,86.571 122.264,86.571 122.264,87.676 121.159,87.676 121.159,88.78 123.369,88.78 123.369,87.676 124.474,87.676 124.474,88.78 125.579,88.78 125.579,87.676 126.684,87.676 126.684,88.78 128.894,88.78 128.894,87.676 127.789,87.676 127.789,86.571 128.894,86.571 128.894,85.466 126.684,85.466 126.684,86.571 125.579,86.571 125.579,84.361 126.684,84.361 126.684,83.256 125.579,83.256 125.579,81.046 126.684,81.046 126.684,82.151 127.789,82.151 127.789,81.046 128.894,81.046 128.894,83.256 127.789,83.256 127.789,84.361 131.103,84.361 131.103,83.256 129.999,83.256 129.999,81.046 131.103,81.046 131.103,82.151 132.208,82.151 132.208,81.046 133.313,81.046 133.313,83.256 132.208,83.256 132.208,84.361 133.313,84.361 133.313,86.571 132.208,86.571 132.208,85.466 129.999,85.466 129.999,86.571 131.103,86.571 131.103,87.676 129.999,87.676 129.999,88.78 132.208,88.78 132.208,87.676 133.313,87.676 133.313,89.885 132.208,89.885 132.208,90.99 133.313,90.99 133.313,93.2 132.208,93.2 132.208,92.095 131.103,92.095 131.103,93.2 129.999,93.2 129.999,90.99 131.103,90.99 131.103,89.885 128.894,89.885 128.894,90.99 127.789,90.99 127.789,89.885 125.579,89.885 125.579,90.99 126.684,90.99 126.684,92.095 125.579,92.095 125.579,93.2 127.789,93.2 127.789,92.095 128.894,92.095 128.894,95.41 127.789,95.41 127.789,94.305 125.579,94.305 125.579,95.41 126.684,95.41 126.684,96.515 125.579,96.515 125.579,97.62 127.789,97.62 127.789,96.515 128.894,96.515 128.894,97.62 131.103,97.62 131.103,96.515 129.999,96.515 129.999,94.305 131.103,94.305 131.103,95.41 132.208,95.41 132.208,94.305 133.313,94.305 133.313,96.515 132.208,96.515 132.208,97.62 135.523,97.62 135.523,96.515 134.418,96.515 134.418,94.305 135.523,94.305 135.523,95.41 136.628,95.41 136.628,94.305 137.733,94.305 137.733,96.515 136.628,96.515 136.628,97.62 138.838,97.62 138.838,96.515 139.943,96.515 139.943,97.62 142.152,97.62 142.152,96.515 141.048,96.515 141.048,95.41 142.152,95.41 142.152,94.305 139.943,94.305 139.943,95.41 138.838,95.41 138.838,92.095 139.943,92.095 139.943,93.2 142.152,93.2 142.152,92.095 141.048,92.095 141.048,90.99 142.152,90.99 142.152,89.885 139.943,89.885 139.943,90.99 138.838,90.99 138.838,89.885 136.628,89.885 136.628,90.99 137.733,90.99 137.733,93.2 136.628,93.2 136.628,92.095 135.523,92.095 135.523,93.2 134.418,93.2 134.418,90.99 135.523,90.99 135.523,89.885 134.418,89.885 134.418,87.676 135.523,87.676 135.523,88.78 137.733,88.78 137.733,87.676 136.628,87.676 136.628,86.571 137.733,86.571 137.733,85.466 135.523,85.466 135.523,86.571 134.418,86.571 134.418,84.361 135.523,84.361 135.523,83.256 134.418,83.256 134.418,81.046 135.523,81.046 135.523,82.151 136.628,82.151 136.628,81.046 137.733,81.046 137.733,83.256 136.628,83.256 136.628,84.361 139.943,84.361 139.943,83.256 138.838,83.256 138.838,81.046 139.943,81.046 139.943,82.151 141.048,82.151 141.048,81.046 142.152,81.046 142.152,83.256 141.048,83.256 141.048,84.361 142.152,84.361 142.152,86.571 141.048,86.571 141.048,85.466 138.838,85.466 138.838,86.571 139.943,86.571 139.943,87.676 138.838,87.676 138.838,88.78 141.048,88.78 141.048,87.676 142.152,87.676 142.152,88.78 143.257,88.78 143.257,87.676 144.362,87.676 144.362,88.78 146.572,88.78 146.572,87.676 145.467,87.676 145.467,86.571 146.572,86.571 146.572,85.466 144.362,85.466 144.362,86.571 143.257,86.571 143.257,84.361 144.362,84.361 144.362,83.256 143.257,83.256 143.257,81.046 144.362,81.046 144.362,82.151 145.467,82.151 145.467,81.046 146.572,81.046 146.572,83.256 145.467,83.256 145.467,84.361 148.782,84.361 148.782,83.256 147.677,83.256 147.677,81.046 148.782,81.046 148.782,82.151 149.887,82.151 149.887,81.046 150.992,81.046 150.992,83.256 149.887,83.256 149.887,84.361 150.992,84.361 150.992,86.571 149.887,86.571 149.887,85.466 147.677,85.466 147.677,86.571 148.782,86.571 148.782,87.676 147.677,87.676 147.677,88.78 149.887,88.78 149.887,87.676 150.992,87.676 150.992,89.885 149.887,89.885 149.887,90.99 150.992,90.99 150.992,93.2 149.887,93.2 149.887,92.095 148.782,92.095 148.782,93.2 147.677,93.2 147.677,90.99 148.782,90.99 148.782,89.885 146.572,89.885 146.572,90.99 145.467,90.99 145.467,89.885 143.257,89.885 143.257,90.99 144.362,90.99 144.362,92.095 143.257,92.095 143.257,93.2 145.467,93.2 145.467,92.095 146.572,92.095 146.572,95.41 145.467,95.41 145.467,94.305 143.257,94.305 143.257,95.41 144.362,95.41 144.362,96.515 143.257,96.515 143.257,97.62 145.467,97.62 145.467,96.515 146.572,96.515 146.572,97.62 148.782,97.62 148.782,96.515 147.677,96.515 147.677,94.305 148.782,94.305 148.782,95.41 149.887,95.41 149.887,94.305 150.992,94.305 150.992,96.515 149.887,96.515 149.887,97.62 150.992,97.62 150.992,99.829 149.887,99.829 149.887,98.725 147.677,98.725 147.677,99.829 148.782,99.829 148.782,100.934 147.677,100.934 147.677,102.039 149.887,102.039 149.887,100.934 150.992,100.934 150.992,103.144 149.887,103.144 149.887,104.249 150.992,104.249 150.992,106.459 149.887,106.459 149.887,105.354 148.782,105.354 148.782,106.459 147.677,106.459 147.677,104.249 148.782,104.249 148.782,103.144 145.467,103.144 145.467,104.249 146.572,104.249 146.572,106.459 145.467,106.459 145.467,105.354 144.362,105.354 144.362,106.459 143.257,106.459 143.257,104.249 144.362,104.249 144.362,103.144 143.257,103.144 143.257,100.934 144.362,100.934 144.362,102.039 146.572,102.039 146.572,100.934 145.467,100.934 145.467,99.829 146.572,99.829 146.572,98.725 144.362,98.725 144.362,99.829 143.257,99.829 143.257,98.725 141.048,98.725 141.048,99.829 142.152,99.829 142.152,102.039 141.048,102.039 141.048,100.934 139.943,100.934 139.943,102.039 138.838,102.039 138.838,99.829 139.943,99.829 139.943,98.725 137.733,98.725 137.733,99.829 136.628,99.829 136.628,98.725 134.418,98.725 134.418,99.829 135.523,99.829 135.523,100.934 134.418,100.934 134.418,102.039 136.628,102.039 136.628,100.934 137.733,100.934 137.733,104.249 136.628,104.249 136.628,103.144 134.418,103.144 134.418,104.249 135.523,104.249 135.523,105.354 134.418,105.354 134.418,106.459 136.628,106.459 136.628,105.354 137.733,105.354 137.733,106.459 139.943,106.459 139.943,105.354 138.838,105.354 138.838,103.144 139.943,103.144 139.943,104.249 141.048,104.249 141.048,103.144 142.152,103.144 142.152,105.354 141.048,105.354 141.048,106.459 142.152,106.459 142.152,107.564 141.048,107.564 141.048,108.669 142.152,108.669 142.152,110.878 141.048,110.878 141.048,109.774 139.943,109.774 139.943,110.878 138.838,110.878 138.838,108.669 139.943,108.669 139.943,107.564 137.733,107.564 137.733,108.669 136.628,108.669 136.628,107.564 134.418,107.564 134.418,108.669 135.523,108.669 135.523,109.774 134.418,109.774 134.418,110.878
